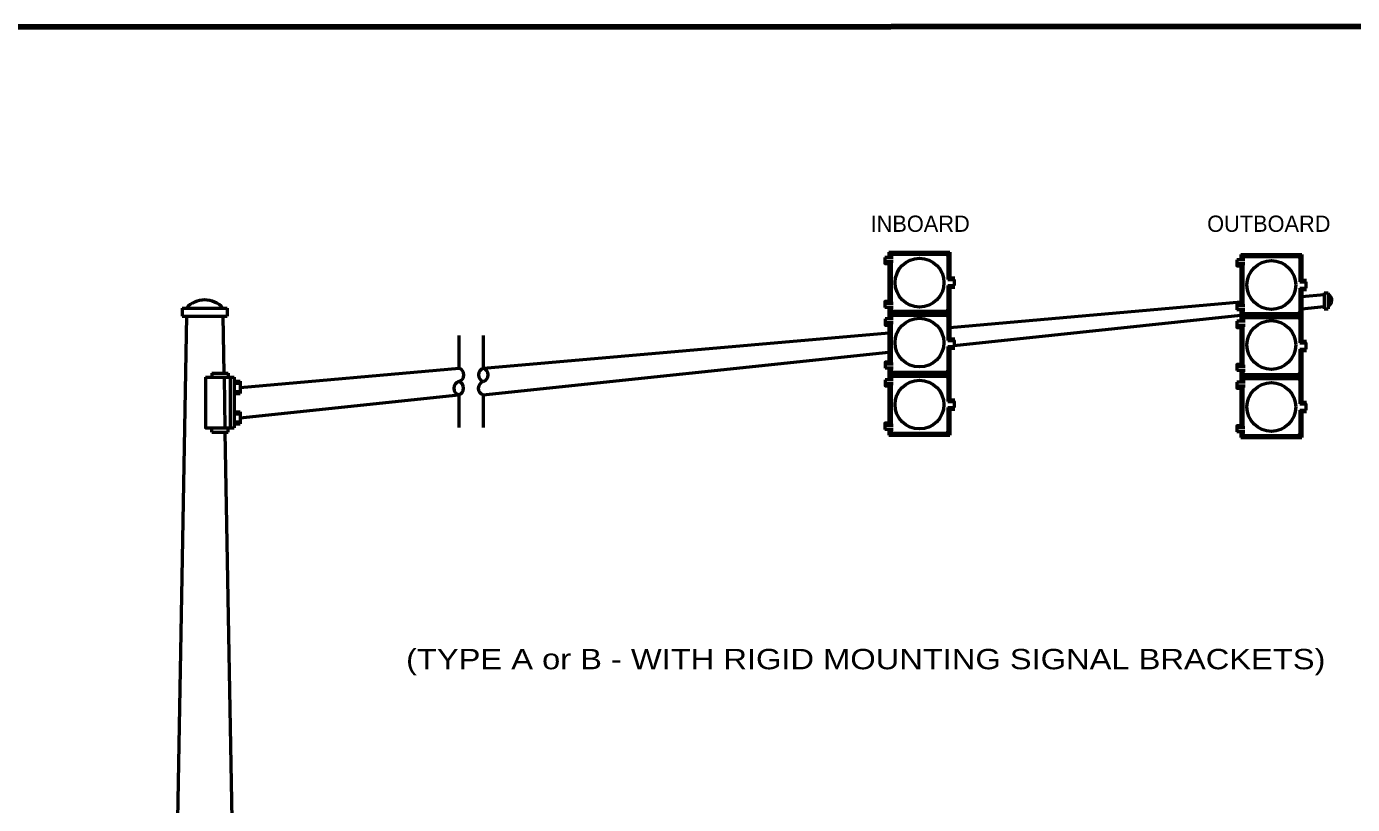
# Model space of a CAD drawing. Extents: x -370 to 486, y -203 to 341.
# Drawn here: x -43.9 to 151.7, y 220.1 to 334.9 of the extents above; entities that cross this region are included whole.
import ezdxf
from ezdxf.enums import TextEntityAlignment as Align

# ---------------------------------------------------------------- set-up
doc = ezdxf.new("R2010")
doc.units = 0
doc.header["$LTSCALE"] = 0.96
doc.layers.add('1', color=7, linetype='Continuous', lineweight=53)

msp = doc.modelspace()

# ---------------------------------------------------------------- linework, layer by layer
at = {"layer": '1'}
for p, q in [((83.2993, 301.6517), (92.2993, 301.6517)), ((83.2993, 301.6517), (83.2993, 300.8597)), ((83.8993, 301.3517), (91.6993, 301.3517)), ((92.2993, 301.6517), (92.2993, 297.6017)), ((135.2024, 301.3042), (144.2024, 301.3042)), ((135.2024, 301.3042), (135.2024, 300.5122)), ((144.2024, 301.3042), (144.2024, 297.2542)), ((83.8993, 300.8597), (82.6993, 300.8597)), ((83.8993, 300.2597), (82.6993, 300.2597)), ((83.2993, 300.2597), (83.2993, 294.0672)), ((83.5993, 301.0517), (83.5993, 300.8597)), ((83.5993, 300.2597), (83.5993, 294.0672)), ((91.9993, 301.0517), (91.9993, 297.6017)), ((135.8024, 300.5122), (134.6024, 300.5122)), ((135.8024, 299.9122), (134.6024, 299.9122)), ((135.2024, 299.9122), (135.2024, 293.7197)), ((135.5024, 300.7042), (135.5024, 300.5122)), ((135.5024, 299.9122), (135.5024, 293.7197)), ((135.8024, 301.0042), (143.6024, 301.0042)), ((143.9024, 300.7042), (143.9024, 297.2542)), ((91.9993, 297.6017), (92.8993, 297.6017)), ((92.7493, 298.0517), (92.7493, 297.6017)), ((92.8993, 297.6017), (92.8993, 296.7017)), ((144.6524, 297.7042), (144.6524, 297.2542)), ((91.9993, 296.7017), (91.9993, 293.2517)), ((91.9993, 296.7017), (92.8993, 296.7017)), ((92.2993, 296.7017), (92.2993, 288.6017)), ((92.7493, 296.7017), (92.7493, 296.2517)), ((143.9024, 297.2542), (144.8024, 297.2542)), ((143.9024, 296.3542), (143.9024, 292.9042)), ((143.9024, 296.3542), (144.8024, 296.3542)), ((144.2024, 296.3542), (144.2024, 288.2542)), ((144.2024, 295.0863), (147.4909, 295.3739)), ((144.6524, 296.3542), (144.6524, 295.9042)), ((144.8024, 297.2542), (144.8024, 296.3542)), ((147.4916, 295.647), (147.4849, 293.2939)), ((147.4916, 295.647), (148.0916, 295.6453)), ((148.0916, 295.6453), (148.0849, 293.2922)), ((-20.9421, 293.3994), (-14.3421, 293.3994)), ((-20.9421, 293.3994), (-20.9421, 292.1994)), ((-14.3421, 293.3994), (-14.3421, 292.1994)), ((83.8993, 294.0672), (82.6993, 294.0672)), ((83.8993, 293.4672), (82.6993, 293.4672)), ((83.2993, 293.4672), (83.2993, 291.7943)), ((83.5993, 293.4672), (83.5993, 293.2517)), ((92.2993, 290.5453), (135.2024, 294.2988)), ((135.8024, 293.7197), (134.6024, 293.7197)), ((144.2024, 293.2811), (147.4859, 293.6262)), ((-20.3421, 292.1994), (-22.562, 165.0188)), ((-20.9421, 292.1994), (-14.3421, 292.1994)), ((-14.9422, 292.1994), (-14.7956, 283.8007)), ((83.9243, 291.7943), (82.7243, 291.7943)), ((83.2993, 292.6517), (92.2993, 292.6517)), ((83.5993, 292.0517), (83.5993, 291.7943)), ((83.8993, 292.9517), (91.6993, 292.9517)), ((83.8993, 292.3517), (91.6993, 292.3517)), ((91.9993, 292.0517), (91.9993, 288.6017)), ((92.8993, 287.8892), (135.2024, 292.3353)), ((135.8024, 293.1197), (134.6024, 293.1197)), ((135.8274, 291.4468), (134.6274, 291.4468)), ((135.2024, 293.1197), (135.2024, 291.4468)), ((135.2024, 292.3042), (144.2024, 292.3042)), ((135.5024, 293.1197), (135.5024, 292.9042)), ((135.5024, 291.7042), (135.5024, 291.4468)), ((135.8024, 292.6042), (143.6024, 292.6042)), ((135.8024, 292.0042), (143.6024, 292.0042)), ((143.9024, 291.7042), (143.9024, 288.2542)), ((147.4849, 293.294), (148.0849, 293.2923)), ((23.4811, 284.5245), (83.2993, 289.7579)), ((83.9243, 291.1943), (82.7243, 291.1943)), ((83.2993, 291.1943), (83.2993, 285.1349)), ((83.5993, 291.1943), (83.5993, 285.1349)), ((135.8274, 290.8468), (134.6274, 290.8468)), ((135.2024, 290.8468), (135.2024, 284.7874)), ((135.5024, 290.8468), (135.5024, 284.7874)), ((19.8811, 284.5245), (19.8811, 289.3245)), ((23.4811, 284.5245), (23.4811, 289.3245)), ((91.9993, 287.7017), (92.8993, 287.7017)), ((91.9993, 287.7017), (91.9993, 284.2517)), ((92.2993, 287.7017), (92.2993, 279.6017)), ((92.7493, 289.0517), (92.7493, 288.6017)), ((92.7493, 287.7017), (92.7493, 287.2517)), ((144.6524, 288.7042), (144.6524, 288.2542)), ((23.4269, 280.5874), (83.2993, 286.8801)), ((143.9024, 287.3542), (144.8024, 287.3542)), ((143.9024, 287.3542), (143.9024, 283.9042)), ((144.2024, 287.3542), (144.2024, 279.2542)), ((144.6524, 287.3542), (144.6524, 286.9042)), ((-16.5956, 283.8007), (-14.1956, 283.8007)), ((-16.5956, 283.8007), (-16.5956, 283.2007)), ((-14.1956, 283.8007), (-14.1956, 283.2007)), ((-12.3956, 281.7007), (19.8811, 284.5245)), ((83.9243, 285.1349), (82.7243, 285.1349)), ((83.9243, 284.5349), (82.7243, 284.5349)), ((83.2993, 284.5349), (83.2993, 282.8103)), ((83.2993, 283.6517), (92.2993, 283.6517)), ((83.5993, 284.5349), (83.5993, 284.2517)), ((83.8993, 283.9517), (91.6993, 283.9517)), ((135.8274, 284.7874), (134.6274, 284.7874)), ((135.8274, 284.1874), (134.6274, 284.1874)), ((135.2024, 284.1874), (135.2024, 282.4628)), ((135.5024, 284.1874), (135.5024, 283.9042)), ((135.8024, 283.6042), (143.6024, 283.6042)), ((-17.4956, 283.2007), (-13.2956, 283.2007)), ((-14.7851, 283.2007), (-14.6542, 275.7007)), ((-13.8956, 283.2007), (-13.8956, 275.7007)), ((-13.2956, 283.2007), (-13.2956, 275.7007)), ((-13.2956, 282.6007), (-12.3956, 282.6007)), ((-13.2956, 282.3007), (-12.3956, 282.3007)), ((-12.3956, 282.6007), (-12.3956, 280.8007)), ((83.9143, 282.8103), (82.7143, 282.8103)), ((83.9143, 282.2103), (82.7143, 282.2103)), ((83.2993, 282.2103), (83.2993, 276.0918)), ((83.5993, 283.0517), (83.5993, 282.8103)), ((83.5993, 282.2103), (83.5993, 276.0918)), ((83.8993, 283.3517), (91.6993, 283.3517)), ((91.9993, 283.0517), (91.9993, 279.6017)), ((135.8174, 282.4628), (134.6174, 282.4628)), ((135.8174, 281.8628), (134.6174, 281.8628)), ((135.2024, 283.3042), (144.2024, 283.3042)), ((135.2024, 281.8628), (135.2024, 275.7443)), ((135.5024, 282.7042), (135.5024, 282.4628)), ((135.5024, 281.8628), (135.5024, 275.7443)), ((135.8024, 283.0042), (143.6024, 283.0042)), ((143.9024, 282.7042), (143.9024, 279.2542)), ((-13.2956, 281.1007), (-12.3956, 281.1007)), ((-13.2956, 280.8007), (-12.3956, 280.8007)), ((-12.3956, 277.2007), (19.8269, 280.5874)), ((19.8269, 280.5874), (19.8269, 275.7874)), ((23.4269, 280.5874), (23.4269, 275.7874)), ((92.7493, 280.0517), (92.7493, 279.6017)), ((144.6524, 279.7042), (144.6524, 279.2542)), ((-13.2956, 278.1007), (-12.3956, 278.1007)), ((-13.2956, 277.8007), (-12.3956, 277.8007)), ((-12.3956, 278.1007), (-12.3956, 276.3007)), ((91.9993, 278.7017), (92.8993, 278.7017)), ((91.9993, 278.7017), (91.9993, 275.2517)), ((92.2993, 278.7017), (92.2993, 274.6517)), ((92.7493, 278.7017), (92.7493, 278.2517)), ((143.9024, 278.3542), (144.8024, 278.3542)), ((143.9024, 278.3542), (143.9024, 274.9042)), ((144.2024, 278.3542), (144.2024, 274.3042)), ((144.6524, 278.3542), (144.6524, 277.9042)), ((-13.2956, 276.6007), (-12.3956, 276.6007)), ((-13.2956, 276.3007), (-12.3956, 276.3007)), ((83.8985, 276.0918), (82.6985, 276.0918)), ((-16.5956, 275.1007), (-16.5956, 275.7007)), ((-16.5956, 275.1007), (-14.1956, 275.1007)), ((-14.6437, 275.1007), (-12.7222, 165.0188)), ((-14.1956, 275.1007), (-14.1956, 275.7007)), ((83.8985, 275.4918), (82.6985, 275.4918)), ((83.2993, 275.4918), (83.2993, 274.6517)), ((83.2993, 274.6517), (92.2993, 274.6517)), ((83.5993, 275.4918), (83.5993, 275.2517)), ((83.8993, 274.9517), (91.6993, 274.9517)), ((135.8016, 275.7443), (134.6016, 275.7443)), ((135.8016, 275.1443), (134.6016, 275.1443)), ((135.2024, 275.1443), (135.2024, 274.3042)), ((135.2024, 274.3042), (144.2024, 274.3042)), ((135.5024, 275.1443), (135.5024, 274.9042)), ((135.8024, 274.6042), (143.6024, 274.6042))]:
    msp.add_line(p, q, dxfattribs=at)
at = {"layer": '1', "lineweight": 158}
msp.add_lwpolyline([(479.406, 334.9398), (-312.294, 334.8398), (-312.194, -191.1602)], dxfattribs=at)
at = {"layer": '1'}
for points in [[(82.6993, 300.8597), (82.6993, 299.9597), (83.2993, 299.9597)], [(134.6024, 300.5122), (134.6024, 299.6122), (135.2024, 299.6122)], [(83.2993, 294.3672), (82.6993, 294.3672), (82.6993, 293.4672)], [(135.2024, 294.0197), (134.6024, 294.0197), (134.6024, 293.1197)], [(82.7243, 291.7943), (82.7243, 290.8943), (83.2993, 290.8943)], [(134.6274, 291.4468), (134.6274, 290.5468), (135.2024, 290.5468)], [(91.9993, 288.6017), (92.8993, 288.6017), (92.8993, 287.7017)], [(143.9024, 288.2542), (144.8024, 288.2542), (144.8024, 287.3542)], [(83.3243, 285.4349), (82.7243, 285.4349), (82.7243, 284.5349)], [(135.2274, 285.0874), (134.6274, 285.0874), (134.6274, 284.1874)], [(-17.4956, 283.2007), (-17.4956, 275.7007), (-13.2956, 275.7007)], [(82.7143, 282.8103), (82.7143, 281.9103), (83.3143, 281.9103)], [(134.6174, 282.4628), (134.6174, 281.5628), (135.2174, 281.5628)], [(91.9993, 279.6017), (92.8993, 279.6017), (92.8993, 278.7017)], [(143.9024, 279.2542), (144.8024, 279.2542), (144.8024, 278.3542)], [(83.2985, 276.3918), (82.6985, 276.3918), (82.6985, 275.4918)], [(135.2016, 276.0443), (134.6016, 276.0443), (134.6016, 275.1443)]]:
    msp.add_lwpolyline(points, dxfattribs=at)
for centre in [(87.803, 297.1482), (139.7062, 296.8007), (87.7962, 288.302), (139.6993, 287.9545), (87.796, 279.1532), (139.699, 278.8057)]:
    msp.add_circle(centre, 3.6, dxfattribs=at)
for centre, radius, start, end in [((83.8993, 301.0518), 0.3, 90, 180), ((91.6993, 301.0518), 0.3, 0, 90), ((135.8024, 300.7043), 0.3, 90, 180), ((143.6024, 300.7043), 0.3, 0, 90), ((147.6708, 294.559), 0.9638, 295.52475, 64.15201), ((-17.6421, 290.9619), 3.6375, 42.07502, 137.92498), ((83.8993, 293.2518), 0.3, 180, 270), ((83.8993, 292.0518), 0.3, 90, 180), ((91.6993, 293.2518), 0.3, 270, 0), ((91.6993, 292.0518), 0.3, 0, 90), ((135.8024, 292.9042), 0.3, 180, 270), ((135.8024, 291.7043), 0.3, 90, 180), ((143.6024, 292.9042), 0.3, 270, 0), ((143.6024, 291.7043), 0.3, 0, 90), ((19.5537, 283.5445), 1.0332, 286.89464, 71.52798), ((23.7814, 283.536), 1.0332, 106.89464, 251.52798), ((23.1546, 283.536), 1.0332, 288.47202, 73.10536), ((83.8993, 284.2518), 0.3, 180, 270), ((91.6993, 284.2518), 0.3, 270, 0), ((135.8024, 283.9042), 0.3, 180, 270), ((143.6024, 283.9042), 0.3, 270, 0), ((20.1534, 281.5759), 1.0332, 108.47202, 253.10536), ((19.5266, 281.5759), 1.0332, 286.89464, 71.52798), ((23.7543, 281.5674), 1.0332, 106.89464, 251.52798), ((83.8993, 283.0518), 0.3, 90, 180), ((91.6993, 283.0518), 0.3, 0, 90), ((135.8024, 282.7043), 0.3, 90, 180), ((143.6024, 282.7043), 0.3, 0, 90), ((83.8993, 275.2518), 0.3, 180, 270), ((91.6993, 275.2518), 0.3, 270, 0), ((135.8024, 274.9042), 0.3, 180, 270), ((143.6024, 274.9042), 0.3, 270, 0)]:
    msp.add_arc(centre, radius, start, end, dxfattribs=at)

# ---------------------------------------------------------------- texts
for s, p in [('INBOARD', (87.899, 304.6429)), ('OUTBOARD', (139.3243, 304.6429))]:
    msp.add_text(s, height=2.4, dxfattribs=at).set_placement(p, align=Align.CENTER)
at = {"layer": '1', "width": 1.2}
msp.add_text('(TYPE A or B - WITH RIGID MOUNTING SIGNAL BRACKETS)', height=3, dxfattribs=at).set_placement((79.8717, 240.1032), align=Align.CENTER)

doc.saveas('drawing.dxf')
